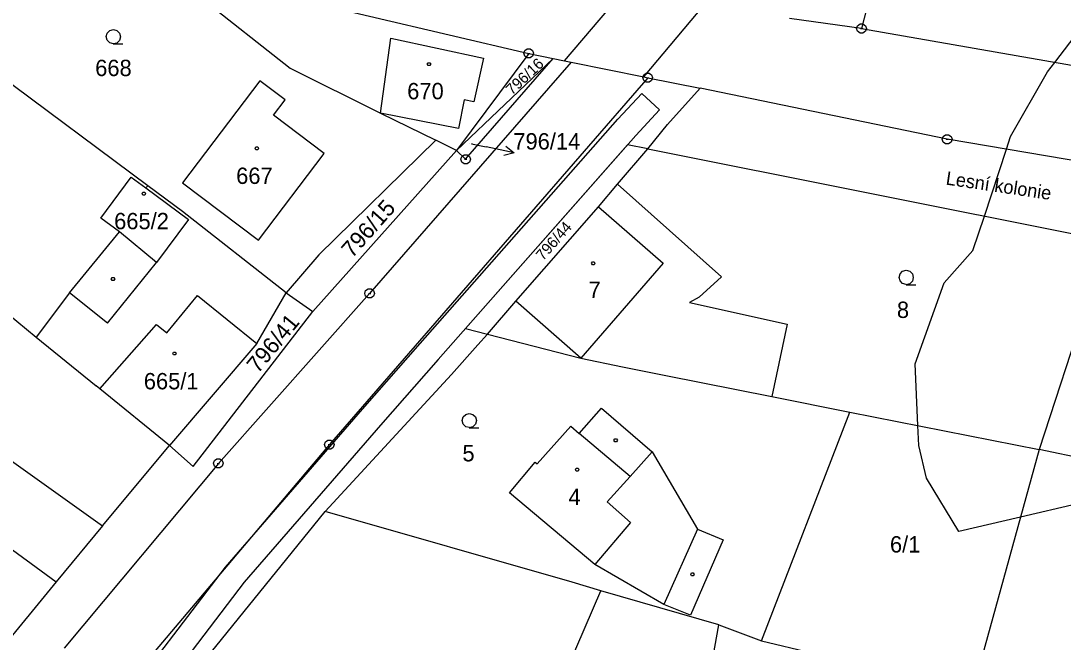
# Model space of a CAD drawing. Extents: x -759060 to -757386, y -1172273 to -1170948.
# Drawn here: x -757983.8 to -757875.5, y -1171226.9 to -1171162.3 of the extents above; entities that cross this region are included whole.
import ezdxf

# ---------------------------------------------------------------- set-up
doc = ezdxf.new("R2010")
doc.units = 0
for name, color, linetype in [('Vrstva 1', 7, 'Continuous'), ('Vrstva 11', 7, 'Continuous'), ('Vrstva 12', 7, 'Continuous'), ('Vrstva 13', 7, 'Continuous'), ('Vrstva 2', 7, 'Continuous'), ('Vrstva 3', 7, 'Continuous'), ('Vrstva 4', 7, 'Continuous'), ('Vrstva 5', 7, 'Continuous'), ('Vrstva 7', 7, 'Continuous'), ('Vrstva 8', 7, 'Continuous')]:
    doc.layers.add(name, color=color, linetype=linetype)

msp = doc.modelspace()

# ---------------------------------------------------------------- linework, layer by layer
at = {"layer": 'Vrstva 1'}
for p, q in [((-757969.07, -1171156.75), (-757955.85, -1171167.2)), ((-757969.07, -1171156.75), (-757931.05, -1171165.68)), ((-757895.33, -1171158.65), (-757896.46, -1171163.1)), ((-757896.46, -1171163.1), (-757903.95, -1171162.06)), ((-757970.63, -1171179.43), (-757992.14, -1171163.45)), ((-757896.46, -1171163.1), (-757858.21, -1171169.78)), ((-757931.05, -1171165.68), (-757938.54, -1171175.78)), ((-757931.05, -1171165.68), (-757928.49, -1171166.2)), ((-757926.64, -1171166.58), (-757947.58, -1171190.64)), ((-757928.49, -1171166.2), (-757938.54, -1171175.78)), ((-757937.6, -1171176.69), (-757928.49, -1171166.2)), ((-757928.49, -1171166.2), (-757927.33, -1171166.44)), ((-757927.33, -1171166.44), (-757926.64, -1171166.58)), ((-757926.64, -1171166.58), (-757919.09, -1171168.13)), ((-757955.85, -1171167.2), (-757946.45, -1171171.9)), ((-757958.99, -1171168.53), (-757967.02, -1171179.14)), ((-757956.37, -1171170.51), (-757958.99, -1171168.53)), ((-757918.67, -1171168.21), (-757951.75, -1171206.35)), ((-757919.09, -1171168.13), (-757918.67, -1171168.21)), ((-757918.67, -1171168.21), (-757913.22, -1171169.31)), ((-757913.22, -1171169.31), (-757916.62, -1171173.08)), ((-757887.56, -1171174.61), (-757913.22, -1171169.31)), ((-757957.58, -1171172.11), (-757956.37, -1171170.51)), ((-757952.31, -1171176.09), (-757957.58, -1171172.11)), ((-757946.45, -1171171.9), (-757940.71, -1171174.71)), ((-757918.68, -1171175.59), (-757916.62, -1171173.08)), ((-757940.71, -1171174.71), (-757952.85, -1171186.63)), ((-757938.54, -1171175.78), (-757940.71, -1171174.71)), ((-757920.78, -1171175.17), (-757937.6, -1171194.28)), ((-757918.68, -1171175.59), (-757920.78, -1171175.17)), ((-757842.26, -1171182.2), (-757887.56, -1171174.61)), ((-757959.14, -1171185.11), (-757952.31, -1171176.09)), ((-757938.54, -1171175.78), (-757953.47, -1171192.51)), ((-757938.54, -1171175.78), (-757937.6, -1171176.69)), ((-757921.82, -1171179.26), (-757918.68, -1171175.59)), ((-757918.68, -1171175.59), (-757870.94, -1171185.14)), ((-757975.5, -1171182.82), (-757972.34, -1171178.54)), ((-757972.34, -1171178.54), (-757970.83, -1171179.65)), ((-757970.83, -1171179.65), (-757970.63, -1171179.43)), ((-757970.83, -1171179.65), (-757966.39, -1171182.94)), ((-757967.03, -1171182.11), (-757970.63, -1171179.43)), ((-757967.02, -1171179.14), (-757959.14, -1171185.11)), ((-757923.8, -1171181.62), (-757921.82, -1171179.26)), ((-757921.82, -1171179.26), (-757911.02, -1171188.91)), ((-757932.38, -1171191.44), (-757923.8, -1171181.62)), ((-757973.58, -1171184.24), (-757975.5, -1171182.82)), ((-757966.39, -1171182.94), (-757969.71, -1171187.43)), ((-757956.24, -1171190.57), (-757967.03, -1171182.11)), ((-757978.77, -1171190.56), (-757973.58, -1171184.24)), ((-757969.71, -1171187.43), (-757973.58, -1171184.24)), ((-757870.94, -1171185.14), (-757878, -1171206.84)), ((-757952.85, -1171186.63), (-757956.24, -1171190.57)), ((-757911.02, -1171188.91), (-757913.34, -1171191.02)), ((-757978.77, -1171190.56), (-757982.22, -1171195.16)), ((-757947.58, -1171190.64), (-757963.29, -1171208.3)), ((-757959.31, -1171195.84), (-757956.24, -1171190.57)), ((-757956.24, -1171190.57), (-757953.47, -1171192.51)), ((-757986.77, -1171191.45), (-757982.22, -1171195.16)), ((-757935.34, -1171194.86), (-757932.38, -1171191.44)), ((-757913.34, -1171191.02), (-757914.34, -1171191.59)), ((-757914.34, -1171191.59), (-757904.2, -1171193.83)), ((-757965.9, -1171208.63), (-757953.47, -1171192.51)), ((-757904.2, -1171193.83), (-757905.78, -1171201.35)), ((-757937.6, -1171194.28), (-757935.34, -1171194.86)), ((-757936.32, -1171195.98), (-757935.34, -1171194.86)), ((-757935.34, -1171194.86), (-757925.63, -1171197.36)), ((-757982.22, -1171195.16), (-757975.99, -1171200.24)), ((-757959.31, -1171195.84), (-757968.37, -1171206.45)), ((-757939.06, -1171199.06), (-757936.32, -1171195.98)), ((-757925.63, -1171197.36), (-757921.31, -1171198.26)), ((-757921.31, -1171198.26), (-757916.79, -1171199.16)), ((-757952.21, -1171213.31), (-757939.06, -1171199.06)), ((-757916.79, -1171199.16), (-757905.78, -1171201.35)), ((-757975.6, -1171200.56), (-757975.99, -1171200.24)), ((-757968.37, -1171206.45), (-757975.6, -1171200.56)), ((-757905.78, -1171201.35), (-757897.68, -1171202.97)), ((-757925.8, -1171205.19), (-757923.48, -1171202.57)), ((-757923.48, -1171202.57), (-757918.21, -1171207.08)), ((-757906.86, -1171226.74), (-757897.68, -1171202.97)), ((-757897.68, -1171202.97), (-757878, -1171206.84)), ((-757930.16, -1171208.33), (-757926.66, -1171204.42)), ((-757926.66, -1171204.42), (-757925.8, -1171205.19)), ((-757975.35, -1171214.79), (-757968.37, -1171206.45)), ((-757951.75, -1171206.35), (-757974.82, -1171233.63)), ((-757968.37, -1171206.45), (-757965.9, -1171208.63)), ((-757878, -1171206.84), (-757884.24, -1171229.48)), ((-757857.03, -1171211.32), (-757878, -1171206.84)), ((-757918.21, -1171207.08), (-757913.52, -1171215.12)), ((-757996.67, -1171208.57), (-757980.14, -1171220.6)), ((-757963.29, -1171208.3), (-757979.33, -1171227.51)), ((-757933.04, -1171211.35), (-757930.36, -1171208.17)), ((-757930.36, -1171208.17), (-757930.16, -1171208.33)), ((-757924.16, -1171218.82), (-757933.04, -1171211.35)), ((-757970.17, -1171235.48), (-757952.21, -1171213.31)), ((-757926.53, -1171220.65), (-757952.21, -1171213.31)), ((-757975.35, -1171214.79), (-757980.14, -1171220.6)), ((-757913.52, -1171215.12), (-757910.83, -1171216.25)), ((-757910.83, -1171216.25), (-757914.24, -1171224.09)), ((-757916.99, -1171222.98), (-757924.16, -1171218.82)), ((-757980.14, -1171220.6), (-757987.99, -1171230.18)), ((-757923.54, -1171221.53), (-757926.53, -1171220.65)), ((-757933.78, -1171245.28), (-757923.54, -1171221.53)), ((-757911.3, -1171225.09), (-757923.54, -1171221.53)), ((-757914.24, -1171224.09), (-757916.99, -1171222.98)), ((-757916.76, -1171255.3), (-757911.3, -1171225.09)), ((-757911.3, -1171225.09), (-757906.86, -1171226.74)), ((-757906.86, -1171226.74), (-757901.62, -1171227.99))]:
    msp.add_line(p, q, dxfattribs=at)
at = {"layer": 'Vrstva 11'}
for p, q in [((-757876.37, -1171166.61), (-757873.27, -1171162.53)), ((-757877.12, -1171167.59), (-757876.37, -1171166.61)), ((-757880.98, -1171174.33), (-757877.12, -1171167.59)), ((-757881.41, -1171175.64), (-757880.98, -1171174.33)), ((-757883.7, -1171182.59), (-757881.41, -1171175.64)), ((-757884.88, -1171186.16), (-757883.7, -1171182.59)), ((-757887.87, -1171189.52), (-757884.88, -1171186.16)), ((-757890.89, -1171197.96), (-757887.87, -1171189.52)), ((-757890.61, -1171204.36), (-757890.89, -1171197.96)), ((-757890.52, -1171206.44), (-757890.61, -1171204.36)), ((-757889.7, -1171209.83), (-757890.52, -1171206.44)), ((-757886.34, -1171215.37), (-757889.7, -1171209.83)), ((-757874.02, -1171212.5), (-757879.94, -1171213.88)), ((-757879.94, -1171213.88), (-757886.34, -1171215.37))]:
    msp.add_line(p, q, dxfattribs=at)
at = {"layer": 'Vrstva 12'}
for p, q in [((-757946.45, -1171171.9), (-757945.37, -1171164.08)), ((-757945.37, -1171164.08), (-757935.76, -1171166.17)), ((-757935.76, -1171166.17), (-757936.75, -1171170.72)), ((-757958.99, -1171168.53), (-757967.02, -1171179.14)), ((-757956.37, -1171170.51), (-757958.99, -1171168.53)), ((-757957.58, -1171172.11), (-757956.37, -1171170.51)), ((-757937.77, -1171170.51), (-757938.34, -1171173.47)), ((-757936.75, -1171170.72), (-757937.77, -1171170.51)), ((-757952.31, -1171176.09), (-757957.58, -1171172.11)), ((-757938.34, -1171173.47), (-757946.45, -1171171.9)), ((-757959.14, -1171185.11), (-757952.31, -1171176.09)), ((-757975.5, -1171182.82), (-757972.34, -1171178.54)), ((-757972.34, -1171178.54), (-757970.83, -1171179.65)), ((-757970.83, -1171179.65), (-757966.39, -1171182.94)), ((-757967.02, -1171179.14), (-757959.14, -1171185.11)), ((-757932.38, -1171191.44), (-757923.8, -1171181.62)), ((-757923.8, -1171181.62), (-757917.07, -1171187.47)), ((-757973.58, -1171184.24), (-757975.5, -1171182.82)), ((-757966.39, -1171182.94), (-757969.71, -1171187.43)), ((-757969.71, -1171187.43), (-757973.58, -1171184.24)), ((-757917.07, -1171187.47), (-757925.63, -1171197.36)), ((-757968.66, -1171194.72), (-757965.48, -1171190.86)), ((-757965.48, -1171190.86), (-757959.31, -1171195.84)), ((-757925.63, -1171197.36), (-757932.38, -1171191.44)), ((-757975.6, -1171200.56), (-757969.73, -1171193.86)), ((-757969.73, -1171193.86), (-757968.66, -1171194.72)), ((-757959.31, -1171195.84), (-757968.37, -1171206.45)), ((-757968.37, -1171206.45), (-757975.6, -1171200.56)), ((-757992.25, -1171202.74), (-757975.35, -1171214.79)), ((-757930.16, -1171208.33), (-757926.66, -1171204.42)), ((-757926.66, -1171204.42), (-757925.8, -1171205.19)), ((-757920.52, -1171209.66), (-757925.8, -1171205.19)), ((-757996.67, -1171208.57), (-757980.14, -1171220.6)), ((-757933.04, -1171211.35), (-757930.36, -1171208.17)), ((-757930.36, -1171208.17), (-757930.16, -1171208.33)), ((-757920.52, -1171209.66), (-757922.88, -1171212.29)), ((-757924.16, -1171218.82), (-757933.04, -1171211.35)), ((-757922.88, -1171212.29), (-757920.48, -1171214.44)), ((-757920.48, -1171214.44), (-757924.16, -1171218.82)), ((-757975.35, -1171214.79), (-757980.14, -1171220.6))]:
    msp.add_line(p, q, dxfattribs=at)
at = {"layer": 'Vrstva 13'}
for p, q in [((-757921.79, -1171172.52), (-757919.28, -1171169.84)), ((-757919.28, -1171169.84), (-757917.46, -1171171.54)), ((-757917.46, -1171171.54), (-757919.93, -1171174.2)), ((-757942.32, -1171195.85), (-757921.79, -1171172.52)), ((-757919.93, -1171174.2), (-757940.44, -1171197.51)), ((-757948.31, -1171202.67), (-757942.32, -1171195.85)), ((-757940.44, -1171197.51), (-757946.43, -1171204.31)), ((-757962.55, -1171219.08), (-757948.31, -1171202.67)), ((-757946.43, -1171204.31), (-757960.61, -1171220.66)), ((-757972.39, -1171231.97), (-757962.55, -1171219.08)), ((-757960.61, -1171220.66), (-757970.37, -1171233.45))]:
    msp.add_line(p, q, dxfattribs=at)
at = {"layer": 'Vrstva 3'}
for points in [[(-757974.19, -1171164.68), (-757974.57, -1171164.58), (-757974.84, -1171164.31), (-757974.94, -1171163.94), (-757974.84, -1171163.57), (-757974.57, -1171163.3), (-757974.2, -1171163.2), (-757973.83, -1171163.3), (-757973.56, -1171163.57), (-757973.46, -1171163.95), (-757973.56, -1171164.33), (-757973.83, -1171164.6), (-757974.21, -1171164.7), (-757973.21, -1171164.7)], [(-757891.81, -1171189.7), (-757892.19, -1171189.6), (-757892.46, -1171189.33), (-757892.56, -1171188.96), (-757892.46, -1171188.59), (-757892.19, -1171188.32), (-757891.82, -1171188.22), (-757891.45, -1171188.32), (-757891.18, -1171188.59), (-757891.08, -1171188.97), (-757891.18, -1171189.35), (-757891.45, -1171189.62), (-757891.83, -1171189.72), (-757890.83, -1171189.72)], [(-757937.21, -1171204.58), (-757937.59, -1171204.48), (-757937.86, -1171204.21), (-757937.96, -1171203.84), (-757937.86, -1171203.47), (-757937.59, -1171203.2), (-757937.22, -1171203.1), (-757936.85, -1171203.2), (-757936.58, -1171203.47), (-757936.48, -1171203.85), (-757936.58, -1171204.23), (-757936.85, -1171204.5), (-757937.23, -1171204.6), (-757936.23, -1171204.6)]]:
    msp.add_lwpolyline(points, dxfattribs=at)
at = {"layer": 'Vrstva 4'}
for p, q in [((-757927.33, -1171166.44), (-757920.46, -1171158.39)), ((-757919.09, -1171168.13), (-757911.06, -1171158.53)), ((-757946.45, -1171171.9), (-757945.37, -1171164.08)), ((-757945.37, -1171164.08), (-757935.76, -1171166.17)), ((-757935.76, -1171166.17), (-757936.75, -1171170.72)), ((-757937.77, -1171170.51), (-757938.34, -1171173.47)), ((-757936.75, -1171170.72), (-757937.77, -1171170.51)), ((-757938.34, -1171173.47), (-757946.45, -1171171.9)), ((-757923.8, -1171181.62), (-757917.07, -1171187.47)), ((-757974.81, -1171193.71), (-757969.71, -1171187.43)), ((-757917.07, -1171187.47), (-757925.63, -1171197.36)), ((-757974.81, -1171193.71), (-757978.77, -1171190.56)), ((-757968.66, -1171194.72), (-757965.48, -1171190.86)), ((-757965.48, -1171190.86), (-757959.31, -1171195.84)), ((-757925.63, -1171197.36), (-757932.38, -1171191.44)), ((-757975.6, -1171200.56), (-757969.73, -1171193.86)), ((-757969.73, -1171193.86), (-757968.66, -1171194.72)), ((-757992.25, -1171202.74), (-757975.35, -1171214.79)), ((-757920.52, -1171209.66), (-757925.8, -1171205.19)), ((-757918.21, -1171207.08), (-757920.52, -1171209.66)), ((-757920.52, -1171209.66), (-757922.88, -1171212.29)), ((-757922.88, -1171212.29), (-757920.48, -1171214.44)), ((-757920.48, -1171214.44), (-757924.16, -1171218.82)), ((-757913.52, -1171215.12), (-757916.99, -1171222.98))]:
    msp.add_line(p, q, dxfattribs=at)
at = {"layer": 'Vrstva 5'}
for points in [[(-757941.32, -1171166.65), (-757941.23, -1171166.8), (-757941.32, -1171166.95), (-757941.5, -1171166.95), (-757941.59, -1171166.8), (-757941.5, -1171166.65)], [(-757959.21, -1171175.4), (-757959.12, -1171175.55), (-757959.21, -1171175.7), (-757959.39, -1171175.7), (-757959.48, -1171175.55), (-757959.39, -1171175.4)], [(-757970.95, -1171180.1), (-757970.86, -1171180.25), (-757970.95, -1171180.4), (-757971.13, -1171180.4), (-757971.22, -1171180.25), (-757971.13, -1171180.1)], [(-757924.25, -1171187.35), (-757924.16, -1171187.5), (-757924.25, -1171187.65), (-757924.43, -1171187.65), (-757924.52, -1171187.5), (-757924.43, -1171187.35)], [(-757974.15, -1171188.98), (-757974.06, -1171189.13), (-757974.15, -1171189.28), (-757974.33, -1171189.28), (-757974.42, -1171189.13), (-757974.33, -1171188.98)], [(-757967.77, -1171196.73), (-757967.68, -1171196.88), (-757967.77, -1171197.03), (-757967.95, -1171197.03), (-757968.04, -1171196.88), (-757967.95, -1171196.73)], [(-757921.92, -1171205.75), (-757921.83, -1171205.9), (-757921.92, -1171206.05), (-757922.1, -1171206.05), (-757922.19, -1171205.9), (-757922.1, -1171205.75)], [(-757925.92, -1171208.81), (-757925.83, -1171208.96), (-757925.92, -1171209.11), (-757926.1, -1171209.11), (-757926.19, -1171208.96), (-757926.1, -1171208.81)], [(-757913.94, -1171219.68), (-757913.85, -1171219.83), (-757913.94, -1171219.98), (-757914.12, -1171219.98), (-757914.21, -1171219.83), (-757914.12, -1171219.68)]]:
    msp.add_lwpolyline(points, close=True, dxfattribs=at)
at = {"layer": 'Vrstva 7'}
for p in [(-757936.99, -1171175.09), (-757932.541, -1171176)]:
    msp.add_line(p, (-757935.48, -1171175.4), dxfattribs=at)
msp.add_lwpolyline([(-757933.42, -1171175.31), (-757932.541, -1171176), (-757933.62, -1171176.29)], dxfattribs=at)
at = {"layer": 'Vrstva 8'}
for p, q in [((-757896.58, -1171163.1), (-757896.34, -1171163.1)), ((-757931.17, -1171165.68), (-757930.93, -1171165.68)), ((-757918.79, -1171168.21), (-757918.55, -1171168.21)), ((-757887.68, -1171174.61), (-757887.44, -1171174.61)), ((-757937.72, -1171176.69), (-757937.48, -1171176.69)), ((-757947.7, -1171190.64), (-757947.46, -1171190.64)), ((-757951.87, -1171206.35), (-757951.63, -1171206.35)), ((-757963.41, -1171208.3), (-757963.17, -1171208.3))]:
    msp.add_line(p, q, dxfattribs=at)
for points in [[(-757896.31, -1171162.62), (-757896.06, -1171162.8), (-757895.96, -1171163.09), (-757896.06, -1171163.38), (-757896.31, -1171163.56), (-757896.62, -1171163.56), (-757896.87, -1171163.38), (-757896.97, -1171163.09), (-757896.87, -1171162.8), (-757896.62, -1171162.62)], [(-757930.9, -1171165.2), (-757930.65, -1171165.38), (-757930.55, -1171165.67), (-757930.65, -1171165.96), (-757930.9, -1171166.14), (-757931.21, -1171166.14), (-757931.46, -1171165.96), (-757931.56, -1171165.67), (-757931.46, -1171165.38), (-757931.21, -1171165.2)], [(-757918.52, -1171167.73), (-757918.27, -1171167.91), (-757918.17, -1171168.2), (-757918.27, -1171168.49), (-757918.52, -1171168.67), (-757918.83, -1171168.67), (-757919.08, -1171168.49), (-757919.18, -1171168.2), (-757919.08, -1171167.91), (-757918.83, -1171167.73)], [(-757887.41, -1171174.13), (-757887.16, -1171174.31), (-757887.06, -1171174.6), (-757887.16, -1171174.89), (-757887.41, -1171175.07), (-757887.72, -1171175.07), (-757887.97, -1171174.89), (-757888.07, -1171174.6), (-757887.97, -1171174.31), (-757887.72, -1171174.13)], [(-757937.45, -1171176.21), (-757937.2, -1171176.39), (-757937.1, -1171176.68), (-757937.2, -1171176.97), (-757937.45, -1171177.15), (-757937.76, -1171177.15), (-757938.01, -1171176.97), (-757938.11, -1171176.68), (-757938.01, -1171176.39), (-757937.76, -1171176.21)], [(-757947.43, -1171190.16), (-757947.18, -1171190.34), (-757947.08, -1171190.63), (-757947.18, -1171190.92), (-757947.43, -1171191.1), (-757947.74, -1171191.1), (-757947.99, -1171190.92), (-757948.09, -1171190.63), (-757947.99, -1171190.34), (-757947.74, -1171190.16)], [(-757951.6, -1171205.87), (-757951.35, -1171206.05), (-757951.25, -1171206.34), (-757951.35, -1171206.63), (-757951.6, -1171206.81), (-757951.91, -1171206.81), (-757952.16, -1171206.63), (-757952.26, -1171206.34), (-757952.16, -1171206.05), (-757951.91, -1171205.87)], [(-757963.14, -1171207.82), (-757962.89, -1171208), (-757962.79, -1171208.29), (-757962.89, -1171208.58), (-757963.14, -1171208.76), (-757963.45, -1171208.76), (-757963.7, -1171208.58), (-757963.8, -1171208.29), (-757963.7, -1171208), (-757963.45, -1171207.82)]]:
    msp.add_lwpolyline(points, close=True, dxfattribs=at)

# ---------------------------------------------------------------- texts
at = {"layer": 'Vrstva 2'}
for s, height, p in [('668', 1.7, (-757976.094, -1171168.04)), ('670', 1.7, (-757943.671, -1171170.45)), ('796/14', 0.1, (-757937.21, -1171175.09)), ('667', 1.7, (-757961.444, -1171179.25)), ('665/2', 1.7, (-757974.124, -1171183.96)), ('7', 1.7, (-757924.825, -1171191.1)), ('8', 1.7, (-757892.786, -1171193.18)), ('665/1', 1.7, (-757971.042, -1171200.6)), ('5', 1.7, (-757937.932, -1171208.09)), ('4', 1.7, (-757926.906, -1171212.61)), ('6/1', 1.7, (-757893.507, -1171217.56))]:
    msp.add_text(s, height=height, dxfattribs=at).set_placement(p)
for s, height, rotation, p in [('796/16', 1.14, 43.14372, (-757932.777, -1171170.082)), ('796/15', 1.7, 48.41493, (-757949.39, -1171187.038)), ('796/44', 1.14, 48.816, (-757929.553, -1171187.3)), ('796/41', 1.7, 50.53488, (-757959.179, -1171199.027))]:
    msp.add_text(s, height=height, rotation=rotation, dxfattribs=at).set_placement(p)
at = {"layer": 'Vrstva 7'}
msp.add_text('796/14', height=1.7, dxfattribs=at).set_placement((-757932.644, -1171175.67))
msp.add_text('Lesní kolonie', height=1.4, rotation=351.6242, dxfattribs=at).set_placement((-757887.762, -1171179.309))

doc.saveas('drawing.dxf')
